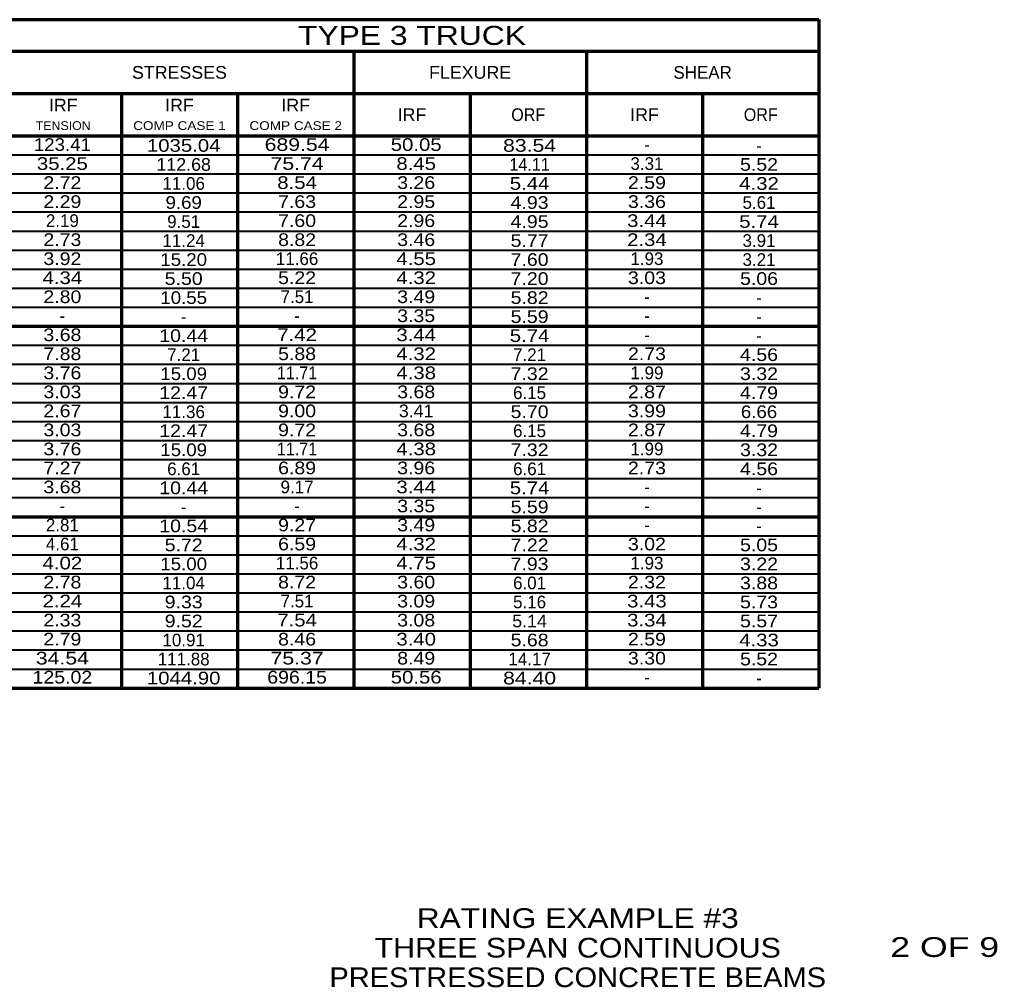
# Model space of a CAD drawing. Extents: x -2055 to -1915, y -81 to 6.
# Drawn here: x -1961.57 to -1915.3, y -80.94 to -35.15 of the extents above; entities that cross this region are included whole.
import ezdxf
from ezdxf.enums import TextEntityAlignment as Align

# ---------------------------------------------------------------- set-up
doc = ezdxf.new("R2010")
doc.units = 0
doc.header["$LTSCALE"] = 0.24
doc.layers.add('1', color=7, linetype='Continuous', lineweight=70)
doc.layers.add('5', color=7, linetype='Continuous', lineweight=40)
doc.layers.add('21', color=7, linetype='Continuous')
doc.layers.add('9', color=7, linetype='Continuous')

msp = doc.modelspace()

# ---------------------------------------------------------------- linework, layer by layer
at = {"layer": '1'}
for p, q in [((-2009.7523, -35.1469), (-1923.7523, -35.1469)), ((-1923.7523, -35.1469), (-1923.7523, -66.7771)), ((-2009.7523, -36.6469), (-1923.7523, -36.6469)), ((-1945.7523, -36.6469), (-1945.7523, -66.7771)), ((-1934.7523, -36.6469), (-1934.7523, -66.7771)), ((-2000.7523, -38.6469), (-1923.7523, -38.6469)), ((-1956.7523, -38.6469), (-1956.7523, -66.7771)), ((-1951.2523, -38.6469), (-1951.2523, -66.7771)), ((-1940.2523, -38.6469), (-1940.2523, -66.7771)), ((-1929.2523, -38.6469), (-1929.2523, -66.7771)), ((-2009.7523, -40.6469), (-1923.7523, -40.6469)), ((-2009.7523, -49.6573), (-1923.7523, -49.6573)), ((-2009.7523, -58.6677), (-1923.7523, -58.6677)), ((-2009.7523, -66.7771), (-1923.7523, -66.7771))]:
    msp.add_line(p, q, dxfattribs=at)
at = {"layer": '5'}
for p, q in [((-2005.7523, -41.5479), (-1923.7523, -41.5479)), ((-2005.7523, -42.449), (-1923.7523, -42.449)), ((-2005.7523, -43.35), (-1923.7523, -43.35)), ((-2005.7523, -44.2511), (-1923.7523, -44.2511)), ((-2005.7523, -45.1521), (-1923.7523, -45.1521)), ((-2005.7523, -46.0532), (-1923.7523, -46.0532)), ((-2005.7523, -46.9542), (-1923.7523, -46.9542)), ((-2005.7523, -47.8552), (-1923.7523, -47.8552)), ((-2005.7523, -48.7563), (-1923.7523, -48.7563)), ((-2005.7523, -50.5583), (-1923.7523, -50.5583)), ((-2005.7523, -51.4594), (-1923.7523, -51.4594)), ((-2005.7523, -52.3604), (-1923.7523, -52.3604)), ((-2005.7523, -53.2615), (-1923.7523, -53.2615)), ((-2005.7523, -54.1625), (-1923.7523, -54.1625)), ((-2005.7523, -55.0636), (-1923.7523, -55.0636)), ((-2005.7523, -55.9646), (-1923.7523, -55.9646)), ((-2005.7523, -56.8657), (-1923.7523, -56.8657)), ((-2005.7523, -57.7667), (-1923.7523, -57.7667)), ((-2005.7523, -59.5688), (-1923.7523, -59.5688)), ((-2005.7523, -60.4698), (-1923.7523, -60.4698)), ((-2005.7523, -61.3708), (-1923.7523, -61.3708)), ((-2005.7523, -62.2719), (-1923.7523, -62.2719)), ((-2005.7523, -63.1729), (-1923.7523, -63.1729)), ((-2005.7523, -64.074), (-1923.7523, -64.074)), ((-2005.7523, -64.975), (-1923.7523, -64.975)), ((-2005.7523, -65.8761), (-1923.7523, -65.8761))]:
    msp.add_line(p, q, dxfattribs=at)

# ---------------------------------------------------------------- texts
at = {"layer": '21'}
for s, height, width, p in [('STRESSES', 0.6, 1.05, (-1954.0022, -37.9469)), ('FLEXURE', 0.6, 1.05, (-1940.2521, -37.9469)), ('IRF', 0.6, 1.05, (-1959.5021, -39.4969)), ('IRF', 0.6, 1.05, (-1954.0021, -39.4969)), ('IRF', 0.6, 1.05, (-1948.5021, -39.4969)), ('IRF', 0.6, 1.05, (-1943.0021, -39.9469)), ('ORF', 0.6, 0.95, (-1937.5022, -39.9469)), ('IRF', 0.6, 1.05, (-1932.0021, -39.9469)), ('ORF', 0.6, 0.95, (-1926.5022, -39.9469)), ('TENSION', 0.4167, 1.05, (-1959.5022, -40.3742)), ('COMP CASE 1', 0.4167, 1.15, (-1954.0022, -40.3742)), ('COMP CASE 2', 0.4167, 1.15, (-1948.5023, -40.3742)), ('RATING EXAMPLE #3', 0.9333, 1.2, (-1935.1602, -78.1282)), ('THREE SPAN CONTINUOUS', 0.9333, 1.15, (-1935.1602, -79.5282)), ('2 OF 9', 0.9333, 1.35, (-1917.7995, -79.4979)), ('PRESTRESSED CONCRETE BEAMS', 0.9333, 1.1, (-1935.1602, -80.9282))]:
    msp.add_text(s, height=height, dxfattribs=dict(at, width=width)).set_placement(p, align=Align.CENTER)
msp.add_text('SHEAR', height=0.6, dxfattribs=at).set_placement((-1929.2522, -37.9469), align=Align.CENTER)
at = {"layer": '9'}
for s, height, width, p in [('TYPE 3 TRUCK', 0.9, 1.25, (-1943.0018, -36.3469)), ('123.41', 0.6, 1.1, (-1959.5419, -41.3615)), ('1035.04', 0.6, 1.2, (-1953.8029, -41.4031)), ('689.54', 0.6, 1.25, (-1948.4381, -41.3615)), ('50.05', 0.6, 1.2, (-1942.803, -41.3615)), ('83.54', 0.6, 1.25, (-1937.4382, -41.4031)), ('35.25', 0.6, 1.2, (-1959.542, -42.2615)), ('112.68', 0.6, 1.05, (-1953.8029, -42.3031)), ('75.74', 0.6, 1.25, (-1948.4381, -42.2615)), ('8.45', 0.6, 1.2, (-1942.803, -42.2615)), ('14.11', 0.6, 0.95, (-1937.4382, -42.3031)), ('5.52', 0.6, 1.15, (-1926.584, -42.3031)), ('2.72', 0.6, 1.15, (-1959.542, -43.1615)), ('8.54', 0.6, 1.2, (-1948.4381, -43.1615)), ('3.26', 0.6, 1.15, (-1942.803, -43.1615)), ('2.59', 0.6, 1.15, (-1931.8864, -43.1615)), ('5.44', 0.6, 1.2, (-1937.4382, -43.2031)), ('4.32', 0.6, 1.2, (-1926.584, -43.2031)), ('2.29', 0.6, 1.15, (-1959.542, -44.0615)), ('7.63', 0.6, 1.15, (-1948.4381, -44.0615)), ('2.95', 0.6, 1.15, (-1942.803, -44.0615)), ('3.36', 0.6, 1.15, (-1931.8864, -44.0615)), ('9.69', 0.6, 1.1, (-1953.8028, -44.1031)), ('4.93', 0.6, 1.15, (-1937.4382, -44.1031)), ('7.60', 0.6, 1.15, (-1948.4381, -44.9615)), ('2.96', 0.6, 1.15, (-1942.803, -44.9615)), ('4.95', 0.6, 1.15, (-1937.4382, -45.0031)), ('3.44', 0.6, 1.2, (-1931.8863, -44.9615)), ('5.74', 0.6, 1.2, (-1926.584, -45.0031)), ('2.73', 0.6, 1.15, (-1959.542, -45.8615)), ('8.82', 0.6, 1.15, (-1948.4381, -45.8615)), ('3.46', 0.6, 1.15, (-1942.803, -45.8615)), ('5.77', 0.6, 1.15, (-1937.4382, -45.9031)), ('2.34', 0.6, 1.2, (-1931.8864, -45.8615)), ('3.92', 0.6, 1.15, (-1959.5419, -46.7615)), ('15.20', 0.6, 1.1, (-1953.8028, -46.8031)), ('4.55', 0.6, 1.2, (-1942.803, -46.7615)), ('7.60', 0.6, 1.15, (-1937.4383, -46.8031)), ('4.34', 0.6, 1.2, (-1959.542, -47.6615)), ('5.50', 0.6, 1.15, (-1953.8028, -47.7031)), ('5.22', 0.6, 1.15, (-1948.4381, -47.6615)), ('4.32', 0.6, 1.2, (-1942.803, -47.6615)), ('7.20', 0.6, 1.15, (-1937.4382, -47.7031)), ('3.03', 0.6, 1.15, (-1931.8863, -47.6615)), ('5.06', 0.6, 1.15, (-1926.5839, -47.7031)), ('2.80', 0.6, 1.15, (-1959.5419, -48.5615)), ('10.55', 0.6, 1.1, (-1953.8028, -48.6031)), ('3.49', 0.6, 1.15, (-1942.803, -48.5615)), ('5.82', 0.6, 1.15, (-1937.4383, -48.6031)), ('3.35', 0.6, 1.15, (-1942.803, -49.4615)), ('5.59', 0.6, 1.15, (-1937.4383, -49.5031)), ('3.68', 0.6, 1.15, (-1959.5419, -50.3615)), ('10.44', 0.6, 1.15, (-1953.8028, -50.4031)), ('7.42', 0.6, 1.2, (-1948.4381, -50.3615)), ('3.44', 0.6, 1.2, (-1942.803, -50.3615)), ('5.74', 0.6, 1.2, (-1937.4382, -50.4031)), ('7.88', 0.6, 1.15, (-1959.542, -51.2615)), ('5.88', 0.6, 1.15, (-1948.4381, -51.2615)), ('4.32', 0.6, 1.2, (-1942.803, -51.2615)), ('2.73', 0.6, 1.15, (-1931.8863, -51.2615)), ('4.56', 0.6, 1.15, (-1926.584, -51.3031)), ('3.76', 0.6, 1.15, (-1959.542, -52.1615)), ('15.09', 0.6, 1.1, (-1953.8028, -52.2031)), ('11.71', 0.6, 0.95, (-1948.4381, -52.1615)), ('4.38', 0.6, 1.2, (-1942.803, -52.1615)), ('7.32', 0.6, 1.15, (-1937.4382, -52.2031)), ('3.32', 0.6, 1.15, (-1926.584, -52.2031)), ('3.03', 0.6, 1.15, (-1959.5419, -53.0615)), ('12.47', 0.6, 1.15, (-1953.8028, -53.1031)), ('9.72', 0.6, 1.15, (-1948.4381, -53.0615)), ('3.68', 0.6, 1.15, (-1942.803, -53.0615)), ('2.87', 0.6, 1.15, (-1931.8863, -53.0615)), ('4.79', 0.6, 1.15, (-1926.584, -53.1031)), ('2.67', 0.6, 1.15, (-1959.5419, -53.9615)), ('9.00', 0.6, 1.15, (-1948.4381, -53.9615)), ('3.41', 0.6, 1.05, (-1942.803, -53.9615)), ('5.70', 0.6, 1.15, (-1937.4382, -54.0031)), ('3.99', 0.6, 1.15, (-1931.8863, -53.9615)), ('6.66', 0.6, 1.1, (-1926.5839, -54.0031)), ('3.03', 0.6, 1.15, (-1959.5419, -54.8615)), ('12.47', 0.6, 1.15, (-1953.8028, -54.9031)), ('9.72', 0.6, 1.15, (-1948.4381, -54.8615)), ('3.68', 0.6, 1.15, (-1942.803, -54.8615)), ('2.87', 0.6, 1.15, (-1931.8863, -54.8615)), ('4.79', 0.6, 1.15, (-1926.584, -54.9031)), ('3.76', 0.6, 1.15, (-1959.542, -55.7615)), ('15.09', 0.6, 1.1, (-1953.8028, -55.8031)), ('11.71', 0.6, 0.95, (-1948.4381, -55.7615)), ('4.38', 0.6, 1.2, (-1942.803, -55.7615)), ('7.32', 0.6, 1.15, (-1937.4382, -55.8031)), ('3.32', 0.6, 1.15, (-1926.584, -55.8031)), ('7.27', 0.6, 1.15, (-1959.5419, -56.6615)), ('6.89', 0.6, 1.15, (-1948.4381, -56.6615)), ('3.96', 0.6, 1.15, (-1942.803, -56.6615)), ('2.73', 0.6, 1.15, (-1931.8863, -56.6615)), ('4.56', 0.6, 1.15, (-1926.584, -56.7031)), ('3.68', 0.6, 1.15, (-1959.5419, -57.5615)), ('10.44', 0.6, 1.15, (-1953.8028, -57.6031)), ('3.44', 0.6, 1.2, (-1942.803, -57.5615)), ('5.74', 0.6, 1.2, (-1937.4382, -57.6031)), ('3.35', 0.6, 1.15, (-1942.803, -58.4615)), ('5.59', 0.6, 1.15, (-1937.4383, -58.5031)), ('9.27', 0.6, 1.15, (-1948.4381, -59.3615)), ('3.49', 0.6, 1.15, (-1942.803, -59.3615)), ('10.54', 0.6, 1.15, (-1953.8028, -59.4031)), ('5.82', 0.6, 1.15, (-1937.4383, -59.4031)), ('6.59', 0.6, 1.15, (-1948.4381, -60.2615)), ('4.32', 0.6, 1.2, (-1942.803, -60.2615)), ('3.02', 0.6, 1.15, (-1931.8863, -60.2615)), ('5.72', 0.6, 1.15, (-1953.8029, -60.3031)), ('7.22', 0.6, 1.15, (-1937.4382, -60.3031)), ('5.05', 0.6, 1.15, (-1926.5839, -60.3031)), ('4.02', 0.6, 1.2, (-1959.5419, -61.1615)), ('15.00', 0.6, 1.1, (-1953.8029, -61.2031)), ('4.75', 0.6, 1.2, (-1942.803, -61.1615)), ('7.93', 0.6, 1.15, (-1937.4382, -61.2031)), ('3.22', 0.6, 1.15, (-1926.584, -61.2031)), ('2.78', 0.6, 1.15, (-1959.542, -62.0615)), ('8.72', 0.6, 1.15, (-1948.4381, -62.0615)), ('3.60', 0.6, 1.15, (-1942.803, -62.0615)), ('2.32', 0.6, 1.15, (-1931.8864, -62.0615)), ('3.88', 0.6, 1.15, (-1926.584, -62.1031)), ('2.24', 0.6, 1.2, (-1959.542, -62.9615)), ('9.33', 0.6, 1.15, (-1953.8028, -63.0031)), ('3.09', 0.6, 1.15, (-1942.803, -62.9615)), ('3.43', 0.6, 1.2, (-1931.8864, -62.9615)), ('5.73', 0.6, 1.15, (-1926.584, -63.0031)), ('2.33', 0.6, 1.15, (-1959.542, -63.8615)), ('9.52', 0.6, 1.15, (-1953.8028, -63.9031)), ('7.54', 0.6, 1.2, (-1948.4381, -63.8615)), ('3.08', 0.6, 1.15, (-1942.803, -63.8615)), ('5.14', 0.6, 1.05, (-1937.4382, -63.9031)), ('3.34', 0.6, 1.2, (-1931.8864, -63.8615)), ('5.57', 0.6, 1.15, (-1926.584, -63.9031)), ('2.79', 0.6, 1.15, (-1959.542, -64.7615)), ('8.46', 0.6, 1.15, (-1948.4381, -64.7615)), ('3.40', 0.6, 1.2, (-1942.803, -64.7615)), ('5.68', 0.6, 1.15, (-1937.4382, -64.8031)), ('2.59', 0.6, 1.15, (-1931.8864, -64.7615)), ('4.33', 0.6, 1.2, (-1926.584, -64.8031)), ('34.54', 0.6, 1.25, (-1959.542, -65.6615)), ('75.37', 0.6, 1.25, (-1948.4381, -65.6615)), ('8.49', 0.6, 1.15, (-1942.803, -65.6615)), ('3.30', 0.6, 1.15, (-1931.8863, -65.6615)), ('5.52', 0.6, 1.15, (-1926.584, -65.7031)), ('125.02', 0.6, 1.15, (-1959.5419, -66.5615)), ('1044.90', 0.6, 1.2, (-1953.8028, -66.6031)), ('696.15', 0.6, 1.15, (-1948.438, -66.5615)), ('50.56', 0.6, 1.2, (-1942.803, -66.5615)), ('84.40', 0.6, 1.25, (-1937.4382, -66.6031))]:
    msp.add_text(s, height=height, dxfattribs=dict(at, width=width)).set_placement(p, align=Align.CENTER)
for s, p in [('-', (-1931.8863, -41.3615)), ('-', (-1926.5839, -41.4031)), ('3.31', (-1931.8863, -42.2615)), ('11.06', (-1953.8028, -43.2031)), ('5.61', (-1926.5839, -44.1031)), ('2.19', (-1959.5419, -44.9615)), ('9.51', (-1953.8028, -45.0031)), ('11.24', (-1953.8028, -45.9031)), ('3.91', (-1926.5839, -45.9031)), ('11.66', (-1948.4381, -46.7615)), ('1.93', (-1931.8863, -46.7615)), ('3.21', (-1926.5839, -46.8031)), ('7.51', (-1948.4381, -48.5615)), ('-', (-1931.8863, -48.5615)), ('-', (-1926.5839, -48.6031)), ('-', (-1959.5419, -49.4615)), ('-', (-1953.8029, -49.5031)), ('-', (-1948.4381, -49.4615)), ('-', (-1931.8863, -49.4615)), ('-', (-1926.5839, -49.5031)), ('-', (-1931.8863, -50.3615)), ('-', (-1926.5839, -50.4031)), ('7.21', (-1953.8028, -51.3031)), ('7.21', (-1937.4382, -51.3031)), ('1.99', (-1931.8863, -52.1615)), ('6.15', (-1937.4382, -53.1031)), ('11.36', (-1953.8028, -54.0031)), ('6.15', (-1937.4382, -54.9031)), ('1.99', (-1931.8863, -55.7615)), ('6.61', (-1953.8029, -56.7031)), ('6.61', (-1937.4382, -56.7031)), ('9.17', (-1948.438, -57.5615)), ('-', (-1931.8863, -57.5615)), ('-', (-1926.5839, -57.6031)), ('-', (-1959.5419, -58.4615)), ('-', (-1953.8029, -58.5031)), ('-', (-1948.4381, -58.4615)), ('-', (-1931.8863, -58.4615)), ('-', (-1926.5839, -58.5031)), ('2.81', (-1959.5419, -59.3615)), ('-', (-1931.8863, -59.3615)), ('-', (-1926.5839, -59.4031)), ('4.61', (-1959.5419, -60.2615)), ('11.56', (-1948.4381, -61.1615)), ('1.93', (-1931.8863, -61.1615)), ('11.04', (-1953.8029, -62.1031)), ('6.01', (-1937.4382, -62.1031)), ('7.51', (-1948.4381, -62.9615)), ('5.16', (-1937.4382, -63.0031)), ('10.91', (-1953.8028, -64.8031)), ('111.88', (-1953.8028, -65.7031)), ('14.17', (-1937.4382, -65.7031)), ('-', (-1931.8863, -66.5615)), ('-', (-1926.5839, -66.6031))]:
    msp.add_text(s, height=0.6, dxfattribs=at).set_placement(p, align=Align.CENTER)

doc.saveas('drawing.dxf')
